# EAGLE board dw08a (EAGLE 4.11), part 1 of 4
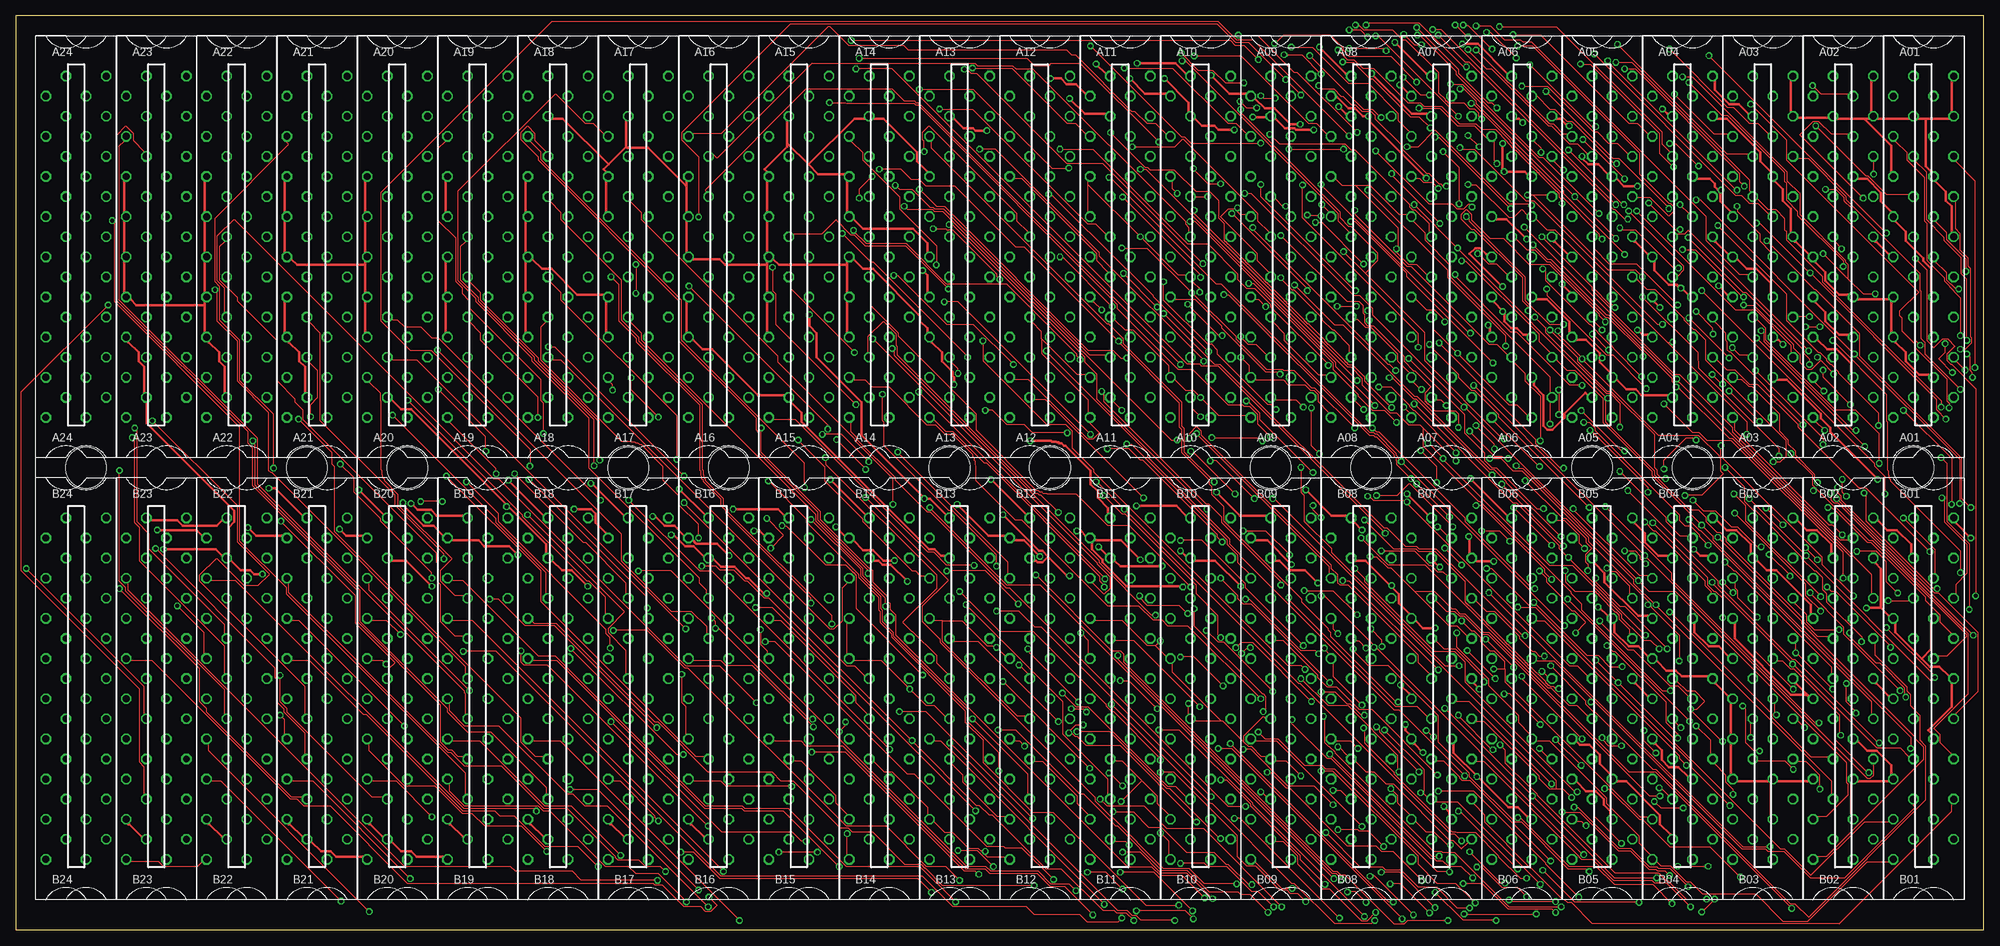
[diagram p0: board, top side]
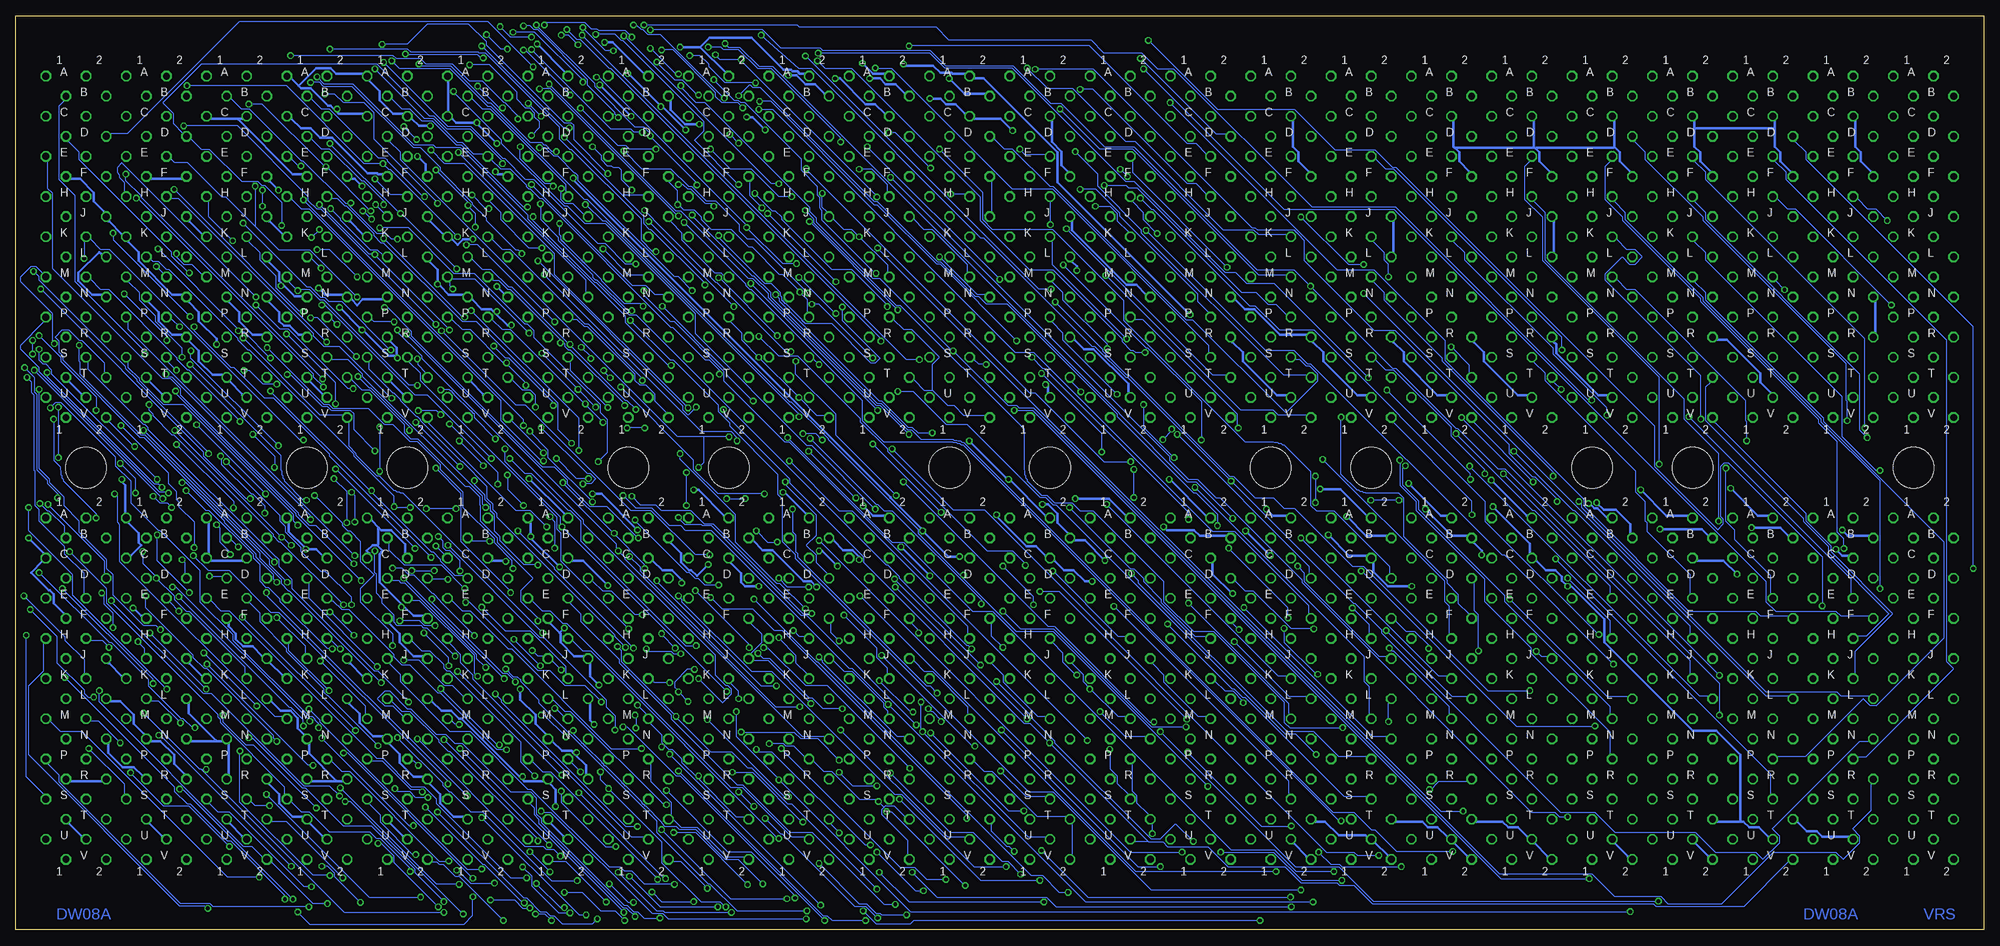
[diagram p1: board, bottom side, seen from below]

Size 311.15 x 144.46 mm. Coordinates in mm from the lower left corner, seen from the top.
Outline: 0,0 311.15,0 311.15,144.46 0,144.46 0,0
Copper layers (1*16): Top 0.035mm / dielectric 1.5mm / Bottom 0.035mm
Design rules "sierraproto": minimum track width 6mil, minimum drill 24mil, track to track 6mil, track to pad 6mil, pad to pad 10mil, via to via 6mil, smd to smd 6mil, copper to edge 25mil, drill to drill 10mil, minimum pad ring 10mil, minimum via ring 8mil, stop-mask expansion 0mil, vias tented up to drill 0mil, thermal gap 10mil
Net classes: 1 supply: width 0.381 mm

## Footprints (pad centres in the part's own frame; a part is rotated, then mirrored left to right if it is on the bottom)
H807 = drill 1.092 octagon: A1 4.763,28.575; A2 -1.587,28.575; B1 1.587,25.4; B2 -4.763,25.4; C1 4.763,22.225; C2 -1.587,22.225; D1 1.587,19.05; D2 -4.763,19.05; E1 4.763,15.875; E2 -1.587,15.875; F1 1.587,12.7; F2 -4.763,12.7; H1 4.763,9.525; H2 -1.587,9.525; J1 1.587,6.35; J2 -4.763,6.35; K1 4.763,3.175; K2 -1.587,3.175; L1 1.587,0; L2 -4.763,0; M1 4.763,-3.175; M2 -1.587,-3.175; N1 1.587,-6.35; N2 -4.763,-6.35; P1 4.763,-9.525; P2 -1.587,-9.525; R1 1.587,-12.7; R2 -4.763,-12.7; S1 4.763,-15.875; S2 -1.587,-15.875; T1 1.587,-19.05; T2 -4.763,-19.05; U1 4.763,-22.225; U2 -1.587,-22.225; V1 1.587,-25.4; V2 -4.763,-25.4
CBLOCK = hole 6.452: 7.938,68.263; 42.862,68.263

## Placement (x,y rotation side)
A01  M903  [H807]  301.62,106.36 0 top
A02  M903  [H807]  288.93,106.36 0 top
A03  M903  [H807]  276.23,106.36 0 top
A04  M903  [H807]  263.52,106.36 0 top
A05  M903  [H807]  250.82,106.36 0 top
A06  M907  [H807]  238.12,106.36 0 top
A07  M651  [H807]  225.43,106.36 0 top
A08  M651  [H807]  212.72,106.36 0 top
A09  M651  [H807]  200.03,106.36 0 top
A10  M651  [H807]  187.32,106.36 0 top
A11  M651  [H807]  174.62,106.36 0 top
A12  M651  [H807]  161.93,106.36 0 top
A13  W011  [H807]  149.22,106.36 0 top
A14  W011  [H807]  136.53,106.36 0 top
A15  W011  [H807]  123.83,106.36 0 top
A16  W011  [H807]  111.12,106.36 0 top
A17  W011  [H807]  98.42,106.36 0 top
A18  W011  [H807]  85.72,106.36 0 top
A19  W011  [H807]  73.03,106.36 0 top
A20  W011  [H807]  60.33,106.36 0 top
A21  W011  [H807]  47.62,106.36 0 top
A22  W011  [H807]  34.92,106.36 0 top
A23  W011  [H807]  22.23,106.36 0 top
A24  H807  [H807]  9.53,106.36 0 top
B01  M903  [H807]  301.62,36.51 0 top
B02  M903  [H807]  288.93,36.51 0 top
B03  M903  [H807]  276.23,36.51 0 top
B04  M903  [H807]  263.52,36.51 0 top
B05  M903  [H807]  250.82,36.51 0 top
B06  M101  [H807]  238.12,36.51 0 top
B07  M907  [H807]  225.43,36.51 0 top
B08  M651  [H807]  212.72,36.51 0 top
B09  M651  [H807]  200.03,36.51 0 top
B10  M651  [H807]  187.32,36.51 0 top
B11  M651  [H807]  174.62,36.51 0 top
B12  M651  [H807]  161.93,36.51 0 top
B13  M651  [H807]  149.22,36.51 0 top
B14  M651  [H807]  136.53,36.51 0 top
B15  M651  [H807]  123.83,36.51 0 top
B16  M517  [H807]  111.12,36.51 0 top
B17  M517  [H807]  98.42,36.51 0 top
B18  M517  [H807]  85.72,36.51 0 top
B19  M517  [H807]  73.03,36.51 0 top
B20  M517  [H807]  60.33,36.51 0 top
B21  M517  [H807]  47.62,36.51 0 top
B22  M517  [H807]  34.92,36.51 0 top
B23  M517  [H807]  22.23,36.51 0 top
B24  H807  [H807]  9.53,36.51 0 top
U$1  [CBLOCK]  3.17,4.76 0 top
U$2  [CBLOCK]  53.98,4.76 0 top
U$3  [CBLOCK]  104.78,4.76 0 top
U$4  [CBLOCK]  155.57,4.76 0 top
U$5  [CBLOCK]  206.38,4.76 0 top
U$6  [CBLOCK]  257.18,4.76 0 top

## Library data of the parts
A01-A09 A10-A24 B01-B09 B10-B24 U$1-U$6 = dec-m

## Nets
-15V [supply]: A07.B2 A08.B2 A09.B2 A10.B2 A11.B2 A12.B2 B08.B2 B09.B2 B10.B2 B11.B2 B12.B2 B13.B2 B14.B2 B15.B2 B16.B2 B17.B2 B18.B2 B19.B2 B20.B2 B21.B2 B22.B2 B23.B2
A06U1: A06.U1 A07.F2 A07.J2 A07.M2 A08.F2 A08.J2 A08.M2 A09.F2 A09.J2 A09.M2 A10.F2 A10.J2 A10.M2 A10.P2 A11.F2 A11.J2 A11.M2 A12.F2 A12.J2 A12.M2 B06.C1
A06V1: A06.V1 A07.P2 A07.T2 A07.V2 A08.P2 A08.T2 A08.V2 A09.P2 A09.T2 A09.V2 A10.T2 A10.V2 A11.P2 A11.T2 A11.V2 A12.P2 A12.T2 A12.V2
B07U1: B07.U1 B08.F2 B08.J2 B08.M2 B08.P2 B08.T2 B08.V2 B09.F2 B09.J2 B09.M2 B09.P2 B09.T2 B09.V2 B10.F2 B10.J2 B10.M2 B11.F2 B11.J2 B11.M2 B12.F2 B12.J2 B12.M2 B13.F2 B13.J2 B13.M2 B14.F2 B14.J2 B14.M2 B15.F2 B15.J2 B15.M2
B07V1: B07.V1 B10.P2 B10.T2 B10.V2 B11.P2 B11.T2 B11.V2 B12.P2 B12.T2 B12.V2 B13.P2 B13.T2 B13.V2 B14.P2 B14.T2 B14.V2 B15.P2
GND [supply]: A01.A1 A01.C1 A01.C2 A01.F1 A01.F2 A01.J2 A01.K1 A01.L2 A01.N1 A01.N2 A01.R1 A01.R2 A01.T1 A01.U2 A02.A1 A02.C1 A02.C2 A02.F1 A02.F2 A02.J2 A02.K1 A02.L2 A02.N1 A02.N2 A02.R1 A02.R2 A02.T1 A02.U2 A03.A1 A03.C1 A03.C2 A03.F1 A03.F2 A03.J2 A03.K1 A03.L2 A03.N1 A03.N2 A03.R1 A03.R2 A03.T1 A03.U2 A04.A1 A04.C1 A04.C2 A04.F1 A04.F2 A04.J2 A04.K1 A04.L2 A04.N1 A04.N2 A04.R1 A04.R2 A04.T1 A04.U2 A05.A1 A05.C1 A05.C2 A05.F1 A05.F2 A05.J2 A05.K1 A05.L2 A05.N1 A05.N2 A05.R1 A05.R2 A05.T1 A05.U2 A06.A1 A06.C1 A06.C2 A06.F1 A06.F2 A06.J2 A06.K1 A06.L2 A06.N1 A06.N2 A06.R1 A06.R2 A06.T1 A06.U2 A07.C2 A08.C2 A09.C2 A10.C2 A11.C2 A12.C2 A13.C2 A13.F2 A13.J2 A13.L2 A13.N2 A13.R2 A13.U2 A14.C2 A14.F2 A14.J2 A14.L2 A14.N2 A14.R2 A14.U2 A15.C2 A15.F2 A15.J2 A15.L2 A15.N2 A15.R2 A15.U2 A16.C2 A16.F2 A16.J2 A16.L2 A16.N2 A16.R2 A16.U2 A17.C2 A17.F2 A17.J2 A17.L2 A17.N2 A17.R2 A17.U2 A18.C2 A18.F2 A18.J2 A18.L2 A18.N2 A18.R2 A18.U2 A19.C2 A19.F2 A19.J2 A19.L2 A19.N2 A19.R2 A19.U2 A20.C2 A20.F2 A20.J2 A20.L2 A20.N2 A20.R2 A20.U2 A21.C2 A21.F2 A21.J2 A21.L2 A21.N2 A21.R2 A21.U2 A22.C2 A22.F2 A22.J2 A22.L2 A22.N2 A22.R2 A22.U2 A23.C2 A23.F2 A23.J2 A23.L2 A23.N2 A23.R2 A23.U2 B01.A1 B01.C1 B01.C2 B01.F1 B01.F2 B01.J2 B01.K1 B01.L2 B01.N1 B01.N2 B01.R1 B01.R2 B01.T1 B01.U2 B02.A1 B02.C1 B02.C2 B02.F1 B02.F2 B02.J2 B02.K1 B02.L2 B02.N1 B02.N2 B02.R1 B02.R2 B02.T1 B02.U2 B03.A1 B03.C1 B03.C2 B03.F1 B03.F2 B03.J2 B03.K1 B03.L2 B03.N1 B03.N2 B03.R1 B03.R2 B03.T1 B03.U2 B04.A1 B04.C1 B04.C2 B04.F1 B04.F2 B04.J2 B04.K1 B04.L2 B04.N1 B04.N2 B04.R1 B04.R2 B04.T1 B04.U2 B05.A1 B05.C1 B05.C2 B05.F1 B05.F2 B05.J2 B05.K1 B05.L2 B05.N1 B05.N2 B05.R1 B05.R2 B05.T1 B05.U2 B06.C2 B06.T1 B07.A1 B07.C1 B07.C2 B07.F1 B07.F2 B07.J2 B07.K1 B07.L2 B07.N1 B07.N2 B07.R1 B07.R2 B07.T1 B07.U2 B08.C2 B09.C2 B10.C2 B11.C2 B12.C2 B13.C2 B14.C2 B15.C2 B16.C2 B16.T2 B16.U2 B16.V2 B17.C2 B17.T2 B17.U2 B17.V2 B18.C2 B18.T2 B18.U2 B18.V2 B19.C2 B19.T2 B19.U2 B19.V2 B20.C2 B20.T2 B20.U2 B20.V2 B21.C2 B21.T2 B21.U2 B21.V2 B22.C2 B22.T2 B22.U2 B23.C2 B23.T2 B23.U2
I_3CYCLE: A05.K2 B05.K2 B19.F2
I_AC00: A03.B1 B03.B1 B16.D2
I_AC01: A03.D1 B03.D1 B16.F2
I_AC02: A03.E1 B03.E1 B16.J2
I_AC03: A03.H1 B03.H1 B16.L2
I_AC04: A03.J1 B03.J1 B16.N2
I_AC05: A03.L1 B03.L1 B16.R2
I_AC06: A03.M1 B03.M1 B17.D2
I_AC07: A03.P1 B03.P1 B17.F2
I_AC08: A03.S1 B03.S1 B17.J2
I_AC09: A03.D2 B03.D2 B17.L2
I_AC10: A03.E2 B03.E2 B17.N2
I_AC11: A03.H2 B03.H2 B17.R2
I_ACCEPT: A04.S2 B04.S2 B07.S2 B15.H2
I_ACCLR: A03.P2 B03.P2 B18.J2
I_ADD00: A04.B1 B04.B1 B20.D2
I_ADD01: A04.D1 B04.D1 B20.F2
I_ADD02: A04.E1 B04.E1 B20.J2
I_ADD03: A04.H1 B04.H1 B20.L2
I_ADD04: A04.J1 B04.J1 B20.N2
I_ADD05: A04.L1 B04.L1 B20.R2
I_ADD06: A04.M1 B04.M1 B21.D2
I_ADD07: A04.P1 B04.P1 B21.F2
I_ADD08: A04.S1 B04.S1 B21.J2
I_ADD09: A04.D2 B04.D2 B21.L2
I_ADD10: A04.E2 B04.E2 B21.N2
I_ADD11: A04.H2 B04.H2 B21.R2
I_BAC00: A01.B1 B01.B1 B07.B1 B10.H2
I_BAC01: A01.D1 B01.D1 B07.D1 B10.N2
I_BAC02: A01.E1 B01.E1 B07.E1 B10.U2
I_BAC03: A01.H1 B01.H1 B07.H1 B11.H2
I_BAC04: A01.J1 B01.J1 B07.J1 B11.N2
I_BAC05: A01.L1 B01.L1 B07.L1 B11.U2
I_BAC06: A01.M1 B01.M1 B07.M1 B12.H2
I_BAC07: A01.P1 B01.P1 B07.P1 B12.N2
I_BAC08: A01.S1 B01.S1 B07.S1 B12.U2
I_BAC09: A01.D2 B01.D2 B07.D2 B13.H2
I_BAC10: A01.E2 B01.E2 B07.E2 B13.N2
I_BAC11: A01.H2 B01.H2 B07.H2 B13.U2
I_BREAK: A04.P2 B04.P2 B07.P2 B14.U2 B22.V2 B23.V2
I_BRKRQ: A04.K2 B04.K2 B18.N2
I_CAINCR: A05.M2 B05.M2 B19.J2
I_DATA00: A05.B1 B05.B1 B22.D2
I_DATA01: A05.D1 B05.D1 B22.F2
I_DATA02: A05.E1 B05.E1 B22.J2
I_DATA03: A05.H1 B05.H1 B22.L2
I_DATA04: A05.J1 B05.J1 B22.N2
I_DATA05: A05.L1 B05.L1 B22.R2
I_DATA06: A05.M1 B05.M1 B23.D2
I_DATA07: A05.P1 B05.P1 B23.F2
I_DATA08: A05.S1 B05.S1 B23.J2
I_DATA09: A05.D2 B05.D2 B23.L2
I_DATA10: A05.E2 B05.E2 B23.N2
I_DATA11: A05.H2 B05.H2 B23.R2
I_DATAIN: A04.M2 B04.M2 B18.R2
I_EXTA0: A05.V2 B05.V2 B19.R2
I_EXTA1: A05.T2 B05.T2 B19.N2
I_EXTA2: A05.S2 B05.S2 B19.L2
I_INIT: A01.V2 A04.V2 B01.V2 B04.V2 B06.N1
I_IOP1: A01.K2 B01.K2 B06.A1
I_IOP2: A01.M2 B01.M2 B06.D1
I_IOP4: A01.P2 B01.P2 B06.F1
I_IRQ: A03.M2 B03.M2 B18.F2
I_LINE: A03.V2 B03.V2 B18.L2
I_MB00: A02.B1 A06.B1 A07.H2 B02.B1
I_MB01: A02.D1 A06.D1 A07.N2 B02.D1
I_MB02: A02.E1 A06.E1 A07.U2 B02.E1
I_MB03: A02.J1 A06.J1 A08.N2 B02.J1
I_MB03\: A02.H1 A06.H1 A08.H2 B02.H1
I_MB04: A02.M1 A06.M1 A09.H2 B02.M1
I_MB04\: A02.L1 A06.L1 A08.U2 B02.L1
I_MB05: A02.S1 A06.S1 A09.U2 B02.S1
I_MB05\: A02.P1 A06.P1 A09.N2 B02.P1
I_MB06: A02.E2 A06.E2 A10.N2 B02.E2
I_MB06\: A02.D2 A06.D2 A10.H2 B02.D2
I_MB07: A02.K2 A06.K2 A11.H2 B02.K2
I_MB07\: A02.H2 A06.H2 A10.U2 B02.H2
I_MB08: A02.P2 A06.P2 A11.U2 B02.P2
I_MB08\: A02.M2 A06.M2 A11.N2 B02.M2
I_MB09: A02.S2 A06.S2 A12.H2 B02.S2
I_MB10: A02.T2 A06.T2 A12.N2 B02.T2
I_MB11: A02.V2 A06.V2 A12.U2 B02.V2
I_MBINCR: A04.T2 B04.T2 B19.D2
I_RUN: A03.S2 B03.S2 B07.K2 B14.H2
I_SKIP: A03.K2 B03.K2 B18.D2
I_TS1: A01.T2 B01.T2 B06.L1
I_TS3: A01.S2 B01.S2 B06.J1
I_TT_INST: A03.T2 B03.T2 B07.M2 B14.N2
I_WCOV: A05.P2 B05.P2 B07.T2 B15.N2
N$1: B06.B1 B08.H2
N$2: B06.E1 B08.N2
N$3: B06.H1 B08.U2
N$4: B06.K1 B09.H2
N$5: B06.M1 B09.N2
N$6: B06.P1 B09.U2
O_3CYCLE: A22.K2 B19.H2
O_AC00: A17.D2 B16.E2
O_AC01: A17.E2 B16.H2
O_AC02: A17.H2 B16.K2
O_AC03: A17.K2 B16.M2
O_AC04: A17.M2 B16.P2
O_AC05: A17.P2 B16.S2
O_AC06: A17.S2 B17.E2
O_AC07: A17.T2 B17.H2
O_AC08: A17.V2 B17.K2
O_AC09: A18.D2 B17.M2
O_AC10: A18.E2 B17.P2
O_AC11: A18.H2 B17.S2
O_ACCEPT: A20.S2 B15.D2
O_ACCLR: A18.P2 B18.K2
O_ADD00: A19.D2 B20.E2
O_ADD01: A19.E2 B20.H2
O_ADD02: A19.H2 B20.K2
O_ADD03: A19.K2 B20.M2
O_ADD04: A19.M2 B20.P2
O_ADD05: A19.P2 B20.S2
O_ADD06: A19.S2 B21.E2
O_ADD07: A19.T2 B21.H2
O_ADD08: A19.V2 B21.K2
O_ADD09: A20.D2 B21.M2
O_ADD10: A20.E2 B21.P2
O_ADD11: A20.H2 B21.S2
O_BAC00: A13.D2 B10.D2
O_BAC01: A13.E2 B10.K2
O_BAC02: A13.H2 B10.S2
O_BAC03: A13.K2 B11.D2
O_BAC04: A13.M2 B11.K2
O_BAC05: A13.P2 B11.S2
O_BAC06: A13.S2 B12.D2
O_BAC07: A13.T2 B12.K2
O_BAC08: A13.V2 B12.S2
O_BAC09: A14.D2 B13.D2
O_BAC10: A14.E2 B13.K2
O_BAC11: A14.H2 B13.S2
O_BREAK: A20.P2 B14.S2
O_BRKRQ: A20.K2 B18.P2
O_CAINCR: A22.M2 B19.K2
O_DATA00: A21.D2 B22.E2
O_DATA01: A21.E2 B22.H2
O_DATA02: A21.H2 B22.K2
O_DATA03: A21.K2 B22.M2
O_DATA04: A21.M2 B22.P2
O_DATA05: A21.P2 B22.S2
O_DATA06: A21.S2 B23.E2
O_DATA07: A21.T2 B23.H2
O_DATA08: A21.V2 B23.K2
O_DATA09: A22.D2 B23.M2
O_DATA10: A22.E2 B23.P2
O_DATA11: A22.H2 B23.S2
O_DATAIN: A20.M2 B18.S2
O_EXTA0: A23.H2 B19.S2
O_EXTA1: A23.E2 B19.P2
O_EXTA2: A23.D2 B19.M2
O_INIT: A14.V2 B09.S2
O_IOP1: A14.K2 B08.D2
O_IOP2: A14.M2 B08.K2
O_IOP4: A14.P2 B08.S2
O_IRQ: A18.M2 B18.H2
O_LINE: A18.V2 B18.M2
O_MB00: A07.D2 A15.D2
O_MB01: A07.K2 A15.E2
O_MB02: A07.S2 A15.H2
O_MB03: A08.K2 A15.M2
O_MB03\: A08.D2 A15.K2
O_MB04: A09.D2 A15.S2
O_MB04\: A08.S2 A15.P2
O_MB05: A09.S2 A15.V2
O_MB05\: A09.K2 A15.T2
O_MB06: A10.K2 A16.E2
O_MB06\: A10.D2 A16.D2
O_MB07: A11.D2 A16.K2
O_MB07\: A10.S2 A16.H2
O_MB08: A11.S2 A16.P2
O_MB08\: A11.K2 A16.M2
O_MB09: A12.D2 A16.S2
O_MB10: A12.K2 A16.T2
O_MB11: A12.S2 A16.V2
O_MBINCR: A20.T2 B19.E2
O_RUN: A18.S2 B14.D2
O_SKIP: A18.K2 B18.E2
O_TS1: A14.T2 B09.K2
O_TS3: A14.S2 B09.D2
O_TT_INST: A18.T2 B14.K2
O_WCOV: A22.P2 B15.K2
VCC [supply]: A06.A2 A07.A2 A08.A2 A09.A2 A10.A2 A11.A2 A12.A2 B06.A2 B07.A2 B08.A2 B09.A2 B10.A2 B11.A2 B12.A2 B13.A2 B14.A2 B15.A2 B16.A2 B17.A2 B18.A2 B19.A2 B20.A2 B21.A2 B22.A2 B23.A2

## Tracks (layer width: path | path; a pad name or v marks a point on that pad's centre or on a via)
-15V  (via drill 0.61)
  Top 0.381: v22.35,63.18 28.57,63.18 29.46,62.29 B22.B2 | v36.7,63.56 37.97,62.29 42.16,62.29 B21.B2 | v51.18,63.31 52.2,62.29 54.86,62.29 B20.B2 | v79.38,59.24 77.98,60.64 74.04,60.64 73.15,61.53 68.96,61.53 B19.B2 67.56,62.29 66.04,63.82 64.52,63.82 61.21,67.12 v61.21,67.5 | v100.71,65.34 101.09,65.34 102.62,63.82 104.14,63.82 105.66,62.29 B16.B2 107.06,61.53 107.57,61.02 110.87,61.02 v112.78,59.12 | v88.27,66.48 90.93,66.48 91.69,65.72 91.69,64.33 93.34,62.67 B17.B2 | v163.58,134.56 165.23,134.56 166.12,133.67 167.64,133.67 169.16,132.14 A11.B2 | v176.15,134.56 178.56,132.14 181.86,132.14 A10.B2 | v188.98,135.06 191.9,132.14 194.56,132.14 A09.B2 195.96,131.38 197.49,129.86 199.01,129.86 201.55,127.32 v203.07,127.32 | v218.82,133.54 220.09,132.27 A07.B2 | A08.B2 208.66,131.89 210.69,129.86 211.71,129.86 212.98,128.59 v213.87,128.59 214.12,128.21 214.12,127.7 v223.01,118.81 | v129.67,63.69 131.06,62.29 B14.B2 132.46,61.53 133.99,60.01 135.51,60.01 137.16,58.36 v138.94,58.36 | v148.84,67.25 153.8,62.29 156.46,62.29 B12.B2 157.86,61.53 159.38,61.53 v161.93,58.99 | v177.8,58.48 174.75,61.53 170.56,61.53 B11.B2 | v201.68,57.72 197.87,61.53 195.96,61.53 B09.B2 | v184.53,54.17 184.4,54.29 175.64,54.29 171.83,58.1 171.83,58.48 170.18,60.13 170.18,61.15 B11.B2 | v167.77,63.06 168.4,63.06 169.16,62.29 B11.B2 | v116.71,63.06 117.6,63.06 118.36,62.29 B15.B2
  Bottom 0.381: v22.35,63.18 21.46,62.29 18.16,62.29 B23.B2 | v36.7,63.56 32.13,63.56 30.86,62.29 B22.B2 | v51.18,63.31 44.58,63.31 43.56,62.29 B21.B2 | v79.38,59.24 79.38,59.88 80.64,61.15 B18.B2 81.66,62.29 84.07,62.29 v88.27,66.48 | v100.71,65.34 97.66,62.29 94.36,62.29 B17.B2 | v61.21,67.5 60.07,66.36 58.17,66.36 55.88,64.07 55.88,62.67 B20.B2 | v163.58,134.56 161.16,132.14 157.86,132.14 A12.B2 | v176.15,134.56 174.5,134.56 173.61,133.67 172.09,133.67 170.56,132.14 A11.B2 | v188.98,135.06 187.71,135.06 186.31,133.67 184.78,133.67 183.26,132.14 A10.B2 | v203.07,127.32 205.36,127.32 207.65,129.6 207.65,131 A08.B2 | v213.87,128.59 v218.82,133.54 | v129.67,63.69 129.16,63.18 124.84,63.18 123.95,62.29 119.76,62.29 B15.B2 | v138.94,58.36 142.11,61.53 143.76,61.53 B13.B2 144.78,62.67 146.43,64.33 146.43,65.72 147.96,67.25 v148.84,67.25 | v177.8,58.48 177.8,58.99 178.82,60.01 180.34,60.01 181.86,61.53 B10.B2 | v201.68,57.72 203.45,55.94 204.34,56.83 204.72,56.83 205.99,58.1 205.99,59.5 207.65,61.15 B08.B2 | v184.53,54.17 185.42,55.05 186.56,55.05 191.52,60.01 193.04,60.01 194.56,61.53 B09.B2 | v161.93,58.99 163.7,58.99 v167.77,63.06 168.02,63.44 172.85,68.26 172.85,68.39 223.01,118.56 v223.01,118.81 | v116.71,63.06 v112.78,59.12
A06U1  (via drill 0.61)
  Top 0.152: v183.64,116.39 182.88,117.16 182.88,118.3 A10.F2 | A12.F2 157.86,118.68 159.13,118.68 170.94,106.87 170.94,105.73 172.72,103.95 A11.M2 | v187.2,100.78 187.2,101.28 186.06,102.42 A10.M2 185.04,103.57 183.77,103.57 v177.8,109.54 169.54,117.79 | 169.54,117.79 169.54,113.47 A11.J2 | 169.54,117.79 169.54,118.3 A11.F2 | v234.95,70.42 v244.73,60.64 | v242.57,79.95 242.57,83.38 A06.U1 242.57,84.9 242.57,87.44 226.82,103.19 226.82,104.97 222.76,109.03 222.76,110.17 220.98,111.95 A07.J2 219.96,113.09 218.69,113.09 214.12,117.67 211.84,117.67 | 193.17,113.47 192.66,113.98 191.77,113.98 190.5,112.71 196.34,106.87 196.34,105.73 198.12,103.95 A09.M2 | 193.17,113.47 193.55,113.09 194.56,113.09 A09.J2 | 193.17,113.47 v193.17,114.11 | A07.M2 223.14,103.57 221.49,105.22 220.22,105.22 218.31,107.12 v218.31,107.63 218.57,108.01 218.57,110.93 211.84,117.67 | 211.84,117.67 209.68,117.67 208.66,118.68 A08.F2 | v224.92,117.16 224.03,118.05 222.63,118.05 222,118.68 221.36,118.68 A07.F2 | v206.5,114.62 207.65,113.47 A08.J2
  Bottom 0.152: A12.J2 156.84,113.47 156.84,118.3 A12.F2 | A11.M2 173.35,103.95 173.35,105.09 v177.8,109.54 178.94,110.68 180.21,110.68 181.86,112.33 A10.J2 182.88,113.47 183.64,114.24 v183.64,116.39 | A10.P2 186.06,97.6 186.06,99.63 v187.2,100.78 187.45,101.16 189.87,103.57 190.37,103.57 194.69,107.89 195.2,107.89 197.99,110.68 201.17,110.68 202.69,112.2 202.69,112.58 203.84,113.73 205.49,113.73 206.12,114.36 v206.5,114.62 206.5,116.78 208.03,118.3 A08.F2 | A12.M2 160.66,103.95 160.66,105.09 166.24,110.68 167.51,110.68 169.16,112.33 A11.J2 | v244.73,60.64 243.46,59.37 243.46,59.24 B06.C1 | v234.95,70.42 234.95,72.33 v242.57,79.95 | A09.M2 199.14,103.57 199.39,103.57 199.64,103.82 200.66,103.82 205.87,109.03 205.87,110.17 207.65,111.95 A08.J2 | v193.17,114.11 195.07,116.01 195.07,118.3 A09.F2 | v218.31,107.63 214.25,103.57 211.84,103.57 A08.M2 | v224.92,117.16 224.92,115.38 224.28,114.75 223.01,114.75 221.36,113.09 A07.J2
A06V1  (via drill 0.61)
  Top 0.152: v219.46,82.61 220.34,81.72 A07.V2 | v222.25,85.41 222.12,85.41 220.98,86.55 A07.T2 220.34,88.08 218.57,89.85 218.57,91 214.38,95.19 213.49,95.19 212.22,96.46 211.84,96.46 A08.P2 | A07.P2 224.16,96.08 224.16,94.93 v227.97,91.12 236.09,83 237.36,83 239.01,81.34 A06.V1 | A08.V2 207.65,81.72 205.87,83.5 205.87,84.64 205.23,85.28 204.72,85.28 203.84,86.17 201.17,86.17 200.41,86.93 195.96,86.93 A09.T2 194.94,88.08 194.94,89.22 v193.68,90.49 | A08.T2 207.26,87.69 205.99,87.69 200.53,93.15 200.53,94.3 198.75,96.08 A09.P2 | 162.18,93.41 162.18,94.55 160.66,96.08 A12.P2 | 162.18,93.41 162.18,91.12 169.54,83.76 169.54,81.72 A11.V2 169.67,80.2 171.32,78.55 170.31,77.53 169.54,77.53 160.15,86.93 157.86,86.93 A12.T2 | 162.18,93.41 167.89,87.69 169.16,87.69 A11.T2 | A11.P2 173.74,96.46 175.39,94.81 176.66,94.81 182.25,89.22 182.25,88.08 A10.T2 183.26,86.93 184.91,85.28 186.18,85.28 v187.32,84.14 190.12,81.34 194.56,81.34 A09.V2
  Bottom 0.152: v219.46,82.61 v222.25,85.41 222.63,85.66 222.63,85.79 v227.97,91.12 | A10.V2 183.26,81.34 184.53,81.34 v187.32,84.14 v193.68,90.49 196.34,93.15 196.34,94.3 198.12,96.08 A09.P2 | 166.24,85.28 163.83,82.87 162.81,82.87 161.29,81.34 157.86,81.34 A12.V2 | 166.24,85.28 167.51,85.28 169.16,86.93 A11.T2 | 166.24,85.28 166.24,89.34 165.1,90.49 169.42,94.81 170.69,94.81 172.34,96.46 A11.P2 | A07.P2 223.14,96.46 222.38,96.46 221.23,95.31 220.73,95.31 213.23,87.82 213.23,86.81 212.47,86.04 211.46,86.04 210.06,84.64 210.06,83.5 208.28,81.72 A08.V2
B07U1  (via drill 0.61)
  Top 0.152: v117.73,47.43 117.73,45.15 118.75,44.13 118.75,43.62 B15.J2 | B15.F2 119.76,48.83 121.03,48.83 132.84,37.02 132.84,35.88 134.62,34.1 B14.M2 | B14.F2 131.44,48.45 131.44,43.62 B14.J2 132.46,42.48 136.91,42.48 v141.35,38.04 144.02,35.37 145.29,35.37 146.94,33.72 B13.M2 | 146.56,48.83 149.61,48.83 153.54,44.9 154.81,44.9 v155.07,44.64 156.46,43.24 B12.J2 | 146.56,48.83 145.16,48.83 B13.F2 | 146.56,48.83 146.56,45.53 158.37,33.72 159.64,33.72 B12.M2 | 180.21,44.9 178.94,44.9 175.01,48.83 170.56,48.83 B11.F2 | 180.21,44.9 181.86,43.24 B10.J2 182.88,42.1 182.88,40.7 190.63,32.96 | 180.21,44.9 v180.97,45.66 | 194.18,29.65 194.94,28.89 195.45,28.89 196.98,27.37 197.74,27.37 B09.P2 199.14,26.61 200.91,26.61 v203.2,24.32 | 194.18,29.65 194.18,30.67 197.23,33.72 197.74,33.21 B09.M2 | 190.63,32.96 190.88,32.96 194.18,29.65 | 190.63,32.96 186.44,32.96 B10.M2 185.42,34.1 v185.42,35.75 | v212.85,35.5 208.28,40.07 208.28,42.1 B08.J2 207.65,43.62 206.88,44.39 v206.88,44.51 | v209.04,46.8 208.28,47.56 208.28,48.45 B08.F2 | v201.8,6.54 200.15,6.54 195.96,10.73 B09.V2 | B07.U1 229.62,13.78 228.6,12.76 227.2,14.16 226.69,14.16 217.81,23.05 216.66,23.05 214.76,24.96 213.49,24.96 211.84,26.61 B08.P2 210.57,27.5 209.17,28.89 v209.04,28.89 | v168.4,46.93 169.54,45.78 169.54,43.62 B11.J2
  Bottom 0.152: v117.73,47.43 118.75,48.45 B15.F2 | 141.22,38.04 142.37,39.18 142.37,40.32 144.15,42.1 B13.J2 | 141.22,38.04 136.91,33.72 135.64,33.72 B14.M2 | B15.M2 122.94,33.72 124.21,33.72 129.67,39.18 129.67,40.32 131.44,42.1 B14.J2 | B12.M2 160.66,34.1 160.66,35.24 166.24,40.83 167.51,40.83 169.16,42.48 B11.J2 | B13.M2 148.34,33.72 149.61,33.72 155.07,39.18 155.07,40.32 156.84,42.1 B12.J2 | v155.07,44.64 156.84,46.42 156.84,48.45 B12.F2 | v141.35,38.04 141.22,38.04 | B11.M2 173.35,34.1 173.35,34.61 173.99,35.24 173.99,35.88 178.94,40.83 180.21,40.83 181.86,42.48 B10.J2 | v180.97,45.66 182.25,46.93 182.25,48.45 B10.F2 | B09.F2 194.94,48.45 193.17,46.67 193.17,45.4 194.94,43.62 B09.J2 194.56,42.48 192.15,42.48 v185.42,35.75 | 203.45,24.07 205.87,26.48 205.87,26.99 207.39,28.51 207.9,28.51 208.66,29.27 | 203.45,24.07 197.23,17.84 195.96,17.84 B09.T2 | 208.66,29.27 209.04,29.65 209.04,30.8 210.82,32.58 B08.M2 211.46,34.1 v212.85,35.5 | v209.04,46.8 209.04,46.67 v206.88,44.51 | B09.V2 195.96,11.49 198.75,11.49 203.45,16.19 205.99,16.19 207.26,17.46 B08.T2 207.52,18.1 207.52,20.13 210.82,23.43 210.82,26.23 B08.P2 | v201.8,6.54 205.99,10.73 207.26,10.73 B08.V2 | 208.66,29.27 v209.04,28.89 | 203.45,24.07 v203.2,24.32 | v168.4,46.93 168.4,47.31 169.54,48.45 B11.F2
B07V1  (via drill 0.61)
  Top 0.152: B12.T2 156.46,17.84 155.19,17.84 149.73,23.3 149.73,24.45 147.96,26.23 B13.P2 | 152.65,12.38 152.15,12.89 150.62,12.89 148.08,15.43 146.81,15.43 145.16,17.08 B13.T2 144.15,18.22 144.15,19.37 138.56,24.96 137.29,24.96 135.64,26.61 B14.P2 | 152.65,12.38 153.54,11.49 156.46,11.49 B12.V2 | v131.44,15.18 131.44,11.87 B14.V2 | B15.P2 122.94,26.61 124.21,26.61 129.67,21.14 129.67,20 131.44,18.22 B14.T2 | 152.65,12.38 v153.29,12.38 | v180.97,15.3 182.25,14.03 182.25,11.87 B10.V2 | 178.05,23.56 180.47,21.14 180.47,20 182.25,18.22 B10.T2 | 178.05,23.56 175.01,26.61 173.74,26.61 B11.P2 | B12.P2 161.04,26.61 162.31,26.61 167.77,21.14 167.77,20 169.54,18.22 B11.T2 | v174.75,20.26 178.05,23.56 | v217.81,4.38 217.04,4.38 v192.02,29.4
  Bottom 0.152: B13.V2 144.15,11.87 144.15,16.7 B13.T2 145.16,17.84 149.61,17.84 156.72,24.96 157.99,24.96 159.64,26.61 B12.P2 | v131.44,15.18 131.44,16.7 B14.T2 132.08,18.22 133.86,20 133.86,21.14 134.62,21.91 134.62,26.23 B14.P2 | v153.29,12.38 154.05,13.14 154.43,13.14 156.84,15.56 156.84,16.7 B12.T2 | v180.97,15.3 180.97,15.43 182.25,16.7 B10.T2 | 173.86,19.37 173.61,19.62 173.48,19.49 172.21,19.49 170.56,17.84 B11.T2 | 173.86,19.37 174.24,18.99 174.24,18.22 170.18,14.16 170.18,11.87 B11.V2 | 173.86,19.37 v174.75,20.26 175.13,20.51 177.67,20.51 182.12,24.96 183.39,24.96 185.04,26.61 B10.P2 186.44,27.37 188.09,29.02 189.36,29.02 189.74,29.4 v192.02,29.4 | v217.81,4.38 224.16,10.73 226.31,10.73 B07.V1
GND  (via drill 0.61)
  Top 0.381: A01.T1 302.51,87.69 300.99,87.69 298.83,89.85 298.83,91.25 297.18,92.9 A01.R2 296.55,94.42 296.55,99.25 A01.N2 296.16,99.63 291.21,99.63 A02.N1 289.81,100.39 288.29,100.39 286.13,102.55 286.13,103.95 284.48,105.6 A02.L2 283.46,106.74 281.43,108.78 281.31,108.78 A03.K1 280.67,110.3 280.67,113.98 279.4,115.25 279.4,117.03 278.13,118.3 A03.F1 277.5,119.83 275.84,121.47 275.84,122.87 270.51,128.21 268.99,128.21 A04.C1 | A02.T1 290.19,88.08 290.19,89.47 287.91,91.76 286.38,91.76 284.86,93.28 A02.R2 | v247.65,122.24 247.65,121.98 248.67,120.97 250.19,120.97 251.71,119.44 A05.F1 253.11,118.68 254.25,117.54 v256.41,117.54 | 235.14,97.79 233.68,99.25 A06.N2 | 235.14,97.79 235.33,97.6 235.33,96.2 236.47,95.06 237.36,95.06 238.38,94.04 239.01,94.04 A06.R1 | v235.08,101.66 229.87,106.87 230.76,107.76 231.52,107.76 232.54,106.74 232.66,106.74 A06.L2 | v232.79,95.57 233.04,95.31 233.04,94.42 A06.R2 | v244.47,102.04 245.75,100.78 A05.N2 | A06.K1 243.21,108.78 243.33,108.78 245.36,106.74 A05.L2 | v238.89,109.16 235.71,112.33 234.06,112.33 A06.J2 | v235.08,97.73 235.14,97.79 | 250.44,90.36 250.44,89.72 252.09,88.08 A05.T1 253.11,86.93 254.63,85.41 256.16,85.41 257.05,84.52 261.24,84.52 A04.U2 | 250.44,90.36 250.44,91.12 248.28,93.28 246.76,93.28 A05.R2 245.75,94.42 245.62,94.55 245.62,96.08 242.06,99.63 240.41,99.63 A06.N1 | v250.82,90.36 250.44,90.36 | v256.41,94.81 257.18,94.04 258.06,94.04 A04.R2 | A06.T1 240.03,86.55 240.03,86.04 241.55,84.52 241.55,79.69 242.19,79.06 242.95,79.06 244.86,80.96 244.86,81.6 248.16,84.9 248.54,84.52 A05.U2
  Top 0.381: A06.F1 239.01,119.44 238.63,119.83 v235.33,119.83 235.08,120.21 v235.08,124.27 | v238.25,127.57 237.62,128.21 237.24,128.21 A06.C2 | v260.35,129.73 261.11,128.97 261.24,128.97 A04.C2 | v245.62,127.06 245.36,127.32 245.11,127.32 244.22,128.21 243.59,128.21 A06.C1 | A05.K1 255.91,108.78 256.03,108.78 258.06,106.74 A04.L2 259.08,105.6 259.08,104.2 261.37,101.92 262.64,101.92 262.89,101.66 v263.27,101.41 263.4,101.41 264.41,100.39 A04.N1 | A04.K1 268.61,108.78 268.73,108.78 270.76,106.74 A03.L2 272.16,105.98 273.69,104.46 275.21,104.46 277.5,102.17 277.5,100.78 A03.N1 | 269.37,116.65 269.49,116.52 269.49,115.13 271.14,113.47 A03.J2 | 269.37,116.65 268.61,117.41 268.61,117.92 267.84,118.68 265.81,118.68 A04.F1 | 269.37,116.65 v269.62,116.9 | v269.24,101.79 270.64,100.39 270.76,100.39 A03.N2 | A03.A1 280.67,134.18 280.67,129.35 A03.C1 281.69,128.33 286.64,128.33 A02.C2 288.04,128.21 292.35,128.21 | A01.A1 306.07,134.18 306.07,129.35 A01.C1 305.69,128.21 302.01,128.21 | 292.35,128.21 292.99,128.21 A02.C1 | A02.A1 293.37,134.18 293.37,129.35 A02.C1 | A01.F2 296.55,119.83 296.55,123.89 292.35,128.08 292.35,128.21 | A02.C1 294.39,128.21 299.34,128.21 A01.C2 300.74,128.21 302.01,128.21 | v279.4,92.52 278.64,93.28 278.51,93.28 A03.R1 | A02.R1 289.81,94.04 288.29,94.04 286.13,96.2 286.13,97.6 284.48,99.25 A02.N2 | A01.R1 302.89,94.42 302.89,99.25 A01.N1 302.89,100.78 302.89,104.46 301.62,105.73 301.62,106.11 298.83,108.9 298.83,110.3 297.18,111.95 A01.J2 296.55,113.47 294.89,115.13 294.89,116.52 292.74,118.68 291.21,118.68 A02.F1 | A02.K1 294,108.78 294.13,108.78 296.16,106.74 A01.L2
  Top 0.381: A01.K1 306.07,110.3 306.07,114.36 305.18,115.25 305.18,116.65 303.53,118.3 A01.F1 302.89,119.83 302.01,120.71 302.01,128.21 | A04.A1 268.61,134.18 268.61,132.78 270.89,130.49 272.42,130.49 273.94,128.97 A03.C2 | v259.97,98.36 259.08,99.25 A04.N2 | B05.N2 246.76,29.78 247.27,29.27 248.79,29.27 250.44,27.62 250.44,26.23 252.09,24.57 B05.R1 253.11,23.43 254.63,23.43 259.97,18.1 259.97,16.7 261.62,15.05 B04.U2 | B04.N2 259.08,29.4 259.21,29.4 260.22,28.38 260.22,26.86 261.37,25.72 262.89,25.72 264.41,24.19 B04.R1 | B04.F1 265.43,48.45 265.43,47.05 267.72,44.77 269.24,44.77 270.76,43.24 B03.J2 | 294.89,50.86 v292.61,50.86 | 294.89,50.86 296.16,49.59 B01.F2 297.18,48.45 297.18,47.05 301.37,42.86 | B01.C2 299.72,59.5 299.72,60.9 297.43,63.18 295.91,63.18 294.39,64.71 B02.A1 | 294.89,50.86 294.89,57.09 294,57.98 B02.C1 | 301.37,42.86 302.89,44.39 302.89,48.45 B01.F1 | 301.37,42.86 302.64,41.59 304.17,41.59 305.69,40.07 B01.K1 306.07,38.92 306.07,35.24 302.39,31.56 303.02,30.92 B01.N1 302.89,29.4 302.89,24.57 B01.R1 302.89,23.05 302.89,18.22 B01.T1 | v309.12,61.91 306.7,64.33 B01.A1 | B02.T1 290.19,18.22 290.19,23.05 B02.R1 291.21,23.43 296.16,23.43 B01.R2 296.55,24.57 296.55,25.97 294.26,28.26 292.74,28.26 291.21,29.78 B02.N1 | 283.08,37.15 283.21,37.15 283.46,36.89 B02.L2 | 283.08,37.15 280.67,37.15 271.78,46.04 271.78,48.45 B03.F2 | B03.K1 281.31,38.92 281.43,38.92 283.08,37.27 283.08,37.15 | B02.K1 294,38.92 294.13,38.92 296.16,36.89 B01.L2 | B03.R1 277.5,23.05 277.5,18.22 B03.T1 | B02.R2 283.46,23.43 278.51,23.43 B03.R1 | B03.R1 277.11,23.43 272.16,23.43 B03.R2 271.14,24.57 271.14,29.4 B03.N2 271.14,30.92 271.14,35.75 B03.L2 270.76,36.89 268.73,38.92 268.61,38.92 B04.K1 267.59,40.07 263.4,40.07 262.51,40.96 260.99,40.96 259.46,42.48 B04.J2 258.06,43.24 256.54,44.77 255.02,44.77 252.73,47.05 252.73,48.45 B05.F1 251.71,49.59 250.32,50.99 v250.19,50.99
  Top 0.381: v193.68,54.29 189.61,58.36 186.44,58.36 B10.C2 185.04,59.12 184.91,59.12 v184.15,59.88 | v229.74,62.17 229.87,62.04 229.87,59.5 B07.C1 230.89,58.36 231.01,58.23 v233.68,58.23 | 217.42,54.29 218.69,53.02 218.69,51.63 220.34,49.97 B07.F2 221.36,48.83 222.5,47.69 v224.41,47.69 | 217.42,54.29 213.36,58.36 211.84,58.36 B08.C2 | 217.42,54.29 v217.55,54.42 | v225.17,57.34 225.04,57.34 224.28,58.1 B07.C2 | v205.87,54.8 203.84,56.83 201.29,56.83 199.77,58.36 199.14,58.36 B09.C2 | B02.F2 283.85,49.97 283.85,51.37 278.38,56.83 276.86,56.83 275.34,58.36 B03.C2 274.32,59.5 274.32,60.9 272.03,63.18 270.51,63.18 268.99,64.71 B04.A1 | B02.C2 287.02,59.5 287.02,60.9 284.73,63.18 283.21,63.18 281.69,64.71 B03.A1 | B04.F2 258.06,49.59 256.54,49.59 251.21,54.93 251.21,56.33 249.56,57.98 B05.C2 | B04.C2 261.24,59.12 259.71,59.12 257.56,61.28 257.56,62.67 255.91,64.33 B05.A1 | v265.3,60.13 266.32,59.12 267.59,59.12 B04.C1 | v225.81,19.49 226.69,18.61 226.69,18.22 B07.T1 | v222.5,28 221.11,29.4 220.98,29.4 B07.N2 220.34,30.92 219.71,31.56 v219.71,32.45 | v231.39,38.04 230.5,38.92 B07.K1 | B05.T1 252.09,18.22 252.09,18.73 251.08,19.75 251.08,20.64 249.81,21.91 248.28,21.91 246.76,23.43 B05.R2 | B05.K1 255.91,38.92 256.03,38.92 258.06,36.89 B04.L2 | 231.08,24.26 235.97,19.37 237.49,19.37 239.01,17.84 B06.T1 | 231.08,24.26 227.33,28 227.33,29.4 B07.N1 | 231.08,24.26 v231.01,24.19 | v218.95,38.67 220.34,37.27 B07.L2 | v294.39,71.18 286.89,78.68 286.89,79.31 285.37,80.83 285.37,81.6 280.04,86.93 278.51,86.93 A03.T1 | A20.R2 55.24,94.42 55.24,99.25 A20.N2 55.24,100.78 55.24,105.09
  Top 0.381: 55.24,105.09 55.24,105.6 A20.L2 55.24,107.12 55.24,111.95 A20.J2 55.24,113.47 55.24,118.3 A20.F2 | A21.F2 42.55,118.3 42.55,113.47 A21.J2 42.55,111.95 42.55,107.12 A21.L2 43.56,105.98 44.45,105.09 55.24,105.09 | A21.N2 42.55,99.25 42.55,94.42 A21.R2 43.18,92.9 44.83,91.25 44.83,89.85 45.72,88.96 45.72,84.9 A21.U2 | 29.84,98.74 29.84,99.25 A22.N2 29.84,100.78 29.84,105.6 A22.L2 29.84,107.12 29.84,111.95 A22.J2 29.84,113.47 29.84,118.3 A22.F2 | 29.84,98.74 29.84,94.42 A22.R2 30.48,92.9 32.13,91.25 32.13,89.85 33.02,88.96 33.02,84.9 A22.U2 | v23.37,60.13 31.62,60.13 32.64,59.12 B22.C2 | v38.99,56.2 37.72,56.2 37.08,56.83 35.56,56.83 34.04,58.36 B22.C2 | A23.R2 17.78,92.9 19.43,91.25 19.43,89.85 20.32,88.96 20.32,84.9 A23.U2 20.7,83.38 20.7,80.07 34.54,66.23 34.54,64.45 33.66,63.56 33.66,59.5 B22.C2 | A23.F2 17.14,118.3 17.14,113.47 A23.J2 17.14,111.95 17.14,107.12 A23.L2 17.14,105.6 17.14,100.78 A23.N2 18.16,99.63 19.05,98.74 29.84,98.74 | B16.T2 106.68,16.7 106.81,16.7 108.84,14.67 B16.U2 | B17.T2 93.98,16.7 94.11,16.7 96.14,14.67 B17.U2 | B18.T2 81.28,16.7 81.41,16.7 83.44,14.67 B18.U2 | B19.T2 68.58,16.7 68.71,16.7 70.74,14.67 B19.U2 | B20.T2 55.88,16.7 56.01,16.7 58.04,14.67 B20.U2 59.44,13.91 60.96,12.38 62.48,12.38 63.37,11.49 67.56,11.49 B19.V2 | B21.T2 43.18,16.7 43.31,16.7 45.34,14.67 B21.U2 46.74,13.91 48.26,12.38 49.78,12.38 50.67,11.49 54.86,11.49 B20.V2 | B23.T2 17.78,16.7 17.91,16.7 19.94,14.67 B23.U2 | B22.T2 30.48,16.7 30.61,16.7 32.64,14.67 B22.U2 | v103.63,62.42 104.01,62.42 105.79,60.64 107.19,60.64 108.84,58.99 B16.C2 110.24,58.61 111.51,57.34 113.67,57.34 115.44,55.56 115.82,55.56 118.24,53.15 v118.75,53.15
  Top 0.381: v65.79,54.29 61.72,58.36 59.44,58.36 B20.C2 | A19.R2 67.94,94.42 67.94,99.25 A19.N2 67.94,100.78 67.94,105.6 A19.L2 | A19.F2 67.94,118.3 67.94,113.47 A19.J2 | 77.72,66.99 62.48,82.23 60.96,82.23 59.44,83.76 A20.U2 | 77.72,66.99 83.82,60.9 83.82,59.5 B18.C2 84.84,58.36 86.36,56.83 87.88,56.83 v90.42,54.29 | 77.72,66.99 v77.6,66.86 | A13.F2 144.15,119.83 142.49,121.47 142.49,122.87 137.16,128.21 135.64,128.21 A14.C2 134.24,128.21 132.59,128.21 125.35,120.97 | v153.54,126.3 151.76,126.3 151.38,126.68 149.86,126.68 148.34,128.21 A13.C2 | v166.62,131.38 169.04,128.97 172.34,128.97 A11.C2 | v181.61,134.56 185.42,130.75 185.42,129.35 A10.C2 186.44,128.21 187.58,127.06 189.48,127.06 190.12,126.43 v192.66,126.43 | v195.58,128.46 197.74,128.46 A09.C2 199.14,128.21 200.66,126.68 202.18,126.68 202.44,126.43 v205.23,126.43 | v209.17,130.11 210.31,128.97 210.44,128.97 A08.C2 | v214.38,135.32 220.73,128.97 223.14,128.97 A07.C2 | A17.R2 93.34,94.42 93.34,99.25 A17.N2 92.96,100.39 88.77,100.39 84.71,104.46 83.19,104.46 81.66,105.98 A18.L2 | A18.R2 80.64,94.42 80.64,99.25 A18.N2 80.64,100.78 80.64,105.6 A18.L2 | A18.L2 80.64,107.12 80.64,111.95 A18.J2 80.64,113.47 80.64,118.3 A18.F2 | v140.97,55.05 138.3,57.72 137.03,57.72 136.4,58.36 135.64,58.36 B14.C2 | 163.19,58.99 162.31,58.1 161.54,58.1 161.29,58.36 161.04,58.36 B12.C2 | 163.19,58.99 162.31,59.88 161.8,59.88 v156.08,65.6 | v171.2,60.52 172.47,59.24 B11.C2 173.74,58.36 174.62,57.47 v181.23,57.47 | v166.62,55.94 166.24,55.94 163.19,58.99 | v148.34,86.17 148.34,87.31 148.08,87.57 148.08,88.2 146.43,89.85 146.43,91.25 144.78,92.9 A13.R2 144.15,94.42 144.15,95.06 143,96.2 143,96.97 135.51,104.46 133.99,104.46 132.46,105.98 A14.L2 131.44,105.6 131.44,105.09
  Top 0.381: A14.R2 131.44,94.42 131.44,99.25 A14.N2 131.44,100.78 131.44,105.09 | A16.N2 106.05,99.25 106.05,94.42 A16.R2 107.06,93.28 108.58,91.76 110.11,91.76 117.35,84.52 121.54,84.52 A15.U2 122.56,83.38 124.21,81.72 124.21,80.33 144.4,60.13 145.29,60.13 146.3,59.12 146.94,59.12 B13.C2 | A17.J2 93.34,113.47 93.34,118.3 A17.F2 93.34,119.83 92.96,120.21 93.73,120.97 | 96.52,123.76 96.52,127.83 A17.C2 | 96.52,123.76 93.73,120.97 | 106.05,117.67 106.05,113.47 A16.J2 106.05,111.95 106.05,107.12 A16.L2 107.06,105.98 111.25,105.98 112.14,105.09 118.75,105.09 | 106.05,117.67 106.05,118.3 A16.F2 | 96.52,123.76 96.65,123.64 99.95,123.64 105.92,117.67 106.05,117.67 | v143.38,104.2 144.15,103.44 144.15,100.78 A13.N2 | A15.R2 118.75,94.42 118.75,99.25 A15.N2 118.75,100.78 118.75,105.09 | 118.75,105.09 118.75,105.6 A15.L2 | A15.L2 118.75,107.12 118.75,111.95 A15.J2 118.75,113.47 118.75,118.3 A15.F2 118.75,119.83 118.36,120.21 121.92,123.76 121.92,124.27 | 121.92,124.27 121.92,127.83 A15.C2 | 125.35,120.97 122.05,124.27 121.92,124.27 | 125.35,120.97 126.87,119.44 131.06,119.44 A14.F2 131.44,118.3 131.44,113.47 A14.J2 132.46,112.33 133.99,110.81 141.86,110.81 144.15,108.52 144.15,107.12 A13.L2 | 131.44,105.09 120.65,105.09 119.76,105.98 A15.L2 | A18.C2 84.84,128.21 86.49,128.21 93.73,120.97
  Bottom 0.381: A01.U2 300.74,84.52 300.74,84.64 302.77,86.68 A01.T1 | A02.U2 288.04,84.52 288.04,84.64 290.07,86.68 A02.T1 | A03.U2 275.34,84.52 275.34,84.64 277.37,86.68 A03.T1 278.51,87.69 280.04,87.69 282.19,89.85 282.19,91.5 283.72,93.03 A02.R2 284.86,94.04 286.38,94.04 288.54,96.2 288.54,97.6 290.19,99.25 A02.N1 | v247.65,122.24 246.38,120.97 246.38,119.83 A05.F2 | v256.41,117.54 257.56,118.68 258.06,118.68 A04.F2 | A02.J2 283.85,111.95 283.72,111.95 281.69,109.92 A03.K1 | A05.F1 253.11,119.44 253.87,119.44 254,119.57 255.52,119.57 261.11,125.16 263.02,125.16 264.54,126.68 266.06,126.68 267.59,128.21 A04.C1 | v235.08,101.66 233.93,100.52 A06.N2 | v232.79,95.57 233.43,95.57 235.33,97.47 | 235.33,97.47 235.97,98.11 237.49,98.11 239.01,99.63 A06.N1 240.41,100.39 242.7,100.39 244.09,101.79 v244.47,102.04 244.47,104.33 245.75,105.6 A05.L2 | v238.89,109.16 240.41,109.16 241.3,108.27 242.19,109.16 A06.K1 243.59,109.92 245.62,111.95 245.75,111.95 A05.J2 | 235.33,97.47 v235.08,97.73 | A04.U2 262.64,84.52 262.64,84.64 264.67,86.68 A04.T1 | A06.U2 237.24,84.52 237.24,84.64 239.27,86.68 A06.T1 | A05.U2 249.94,84.52 249.94,84.64 251.97,86.68 A05.T1 | A05.R1 251.97,93.03 250.95,92.01 250.95,90.49 v250.82,90.36 251.21,90.61 251.33,90.74 252.22,90.74 256.29,94.81 v256.41,94.81 256.79,95.06 256.79,95.19 v259.97,98.36 | v235.33,119.83 234.95,119.44 234.06,119.44 A06.F2 | A06.A1 242.82,134.18 242.82,129.35 A06.C1 242.19,128.21 241.55,127.57 v238.25,127.57 238,127.19 v235.08,124.27 | 260.6,129.48 261.37,130.24 261.75,130.24 264.54,133.03 266.06,133.03 266.45,133.41
  Bottom 0.381: 260.6,129.48 260.1,128.97 256.29,128.97 A05.C1 | 266.45,133.41 267.59,134.56 A04.A1 | 260.6,129.48 v260.35,129.73 | 266.45,133.41 263.65,136.21 261.37,136.21 260.48,135.32 256.29,135.32 A05.A1 255.27,134.18 253.62,132.52 253.62,131.13 251.46,128.97 249.94,128.97 A05.C2 248.54,128.21 247.4,127.06 v245.62,127.06 | A03.R2 272.16,94.04 273.69,94.04 275.84,96.2 275.84,97.6 277.5,99.25 A03.N1 | A04.R1 265.81,94.04 266.45,94.04 267.84,95.44 268.73,95.44 269.49,96.2 269.49,97.6 271.14,99.25 A03.N2 | A04.J2 258.44,111.95 258.32,111.95 256.29,109.92 A05.K1 | A05.N1 253.11,99.63 256.29,99.63 257.18,98.74 258.06,99.63 A04.N2 259.46,100.39 262.25,100.39 v263.27,101.41 | 268.99,102.04 269.49,102.55 269.49,103.95 271.14,105.6 A03.L2 | 268.99,102.04 267.08,100.14 265.81,100.14 A04.N1 | A03.J2 271.14,111.95 271.02,111.95 268.99,109.92 A04.K1 | v269.62,116.9 271.02,118.3 271.14,118.3 A03.F2 | 268.99,102.04 v269.24,101.79 | 275.97,128.21 280.29,128.21 A03.C1 | 275.97,128.21 275.34,128.21 A03.C2 | v279.4,92.52 279.4,93.41 282.19,96.2 282.19,97.6 283.85,99.25 A02.N2 284.86,100.39 286.38,100.39 291.72,105.73 291.72,107.12 293.37,108.78 A02.K1 294.39,109.92 296.42,111.95 296.55,111.95 A01.J2 297.18,113.47 298.83,115.13 298.83,116.52 300.99,118.68 302.51,118.68 A01.F1 | A02.F2 284.86,118.68 289.81,118.68 A02.F1 | A04.F1 265.81,119.44 267.33,119.44 275.97,128.08 275.97,128.21 | A01.N2 297.56,100.39 299.08,100.39 301.24,102.55 301.24,103.82 297.94,107.12 297.56,106.74 A01.L2 | B04.U2 262.64,14.67 262.64,14.8 264.67,16.83 B04.T1 265.81,17.84 267.33,17.84 269.49,20 269.49,21.4 271.14,23.05 B03.R2
  Bottom 0.381: 260.48,23.43 264.41,23.43 B04.R1 | 260.48,23.43 259.46,23.43 B04.R2 | 260.48,23.43 260.48,23.56 264.8,27.88 264.8,29.4 B04.N1 265.56,30.8 266.57,31.81 266.57,33.47 267.72,34.61 269.24,34.61 270.76,36.13 B03.L2 | B03.F1 277.5,48.45 277.5,47.94 276.35,46.8 276.35,45.91 275.21,44.77 273.69,44.77 272.16,43.24 B03.J2 271.02,42.23 268.99,40.2 268.99,40.07 B04.K1 | v292.61,50.86 291.34,49.59 291.21,49.59 B02.F1 | B02.C1 292.99,59.12 291.34,60.77 291.72,61.15 291.72,62.67 293.37,64.33 B02.A1 293.88,65.85 293.88,70.29 294.39,70.8 v294.39,71.18 | B01.F1 303.53,49.97 305.18,51.63 305.18,53.02 305.82,53.66 305.94,53.66 308.74,56.45 306.96,58.23 B01.C1 306.7,59.5 v309.12,61.91 | B01.U2 300.74,14.67 300.74,14.8 302.77,16.83 B01.T1 | B02.U2 288.04,14.67 288.04,14.8 290.07,16.83 B02.T1 | B01.N2 296.55,29.4 296.55,28 294.26,25.72 292.48,25.72 291.08,24.32 B02.R1 | B01.R1 302.51,23.43 297.56,23.43 B01.R2 | B02.J2 283.85,42.1 283.72,42.1 281.69,40.07 B03.K1 | B01.J2 296.55,42.1 296.42,42.1 294.39,40.07 B02.K1 | B03.U2 275.34,14.67 275.34,14.8 277.37,16.83 B03.T1 | B03.R1 277.5,24.57 277.5,29.4 B03.N1 278.51,29.78 279.53,29.78 | 279.53,29.78 283.46,29.78 B02.N2 | B02.R2 284.48,24.57 286.13,26.23 286.13,27.62 288.29,29.78 289.81,29.78 B02.N1 290.83,30.92 292.48,32.58 292.48,33.97 294.64,36.13 296.16,36.13 B01.L2 | B02.L2 283.85,35.75 283.85,34.23 279.53,29.91 279.53,29.78 | v193.68,54.29 195.83,54.29 196.47,54.93 196.47,56.33 198.12,57.98 B09.C2 | B07.A1 229.87,64.33 229.74,64.2 v229.74,62.17 229.49,61.78 229.49,61.66 v225.17,57.34 | v233.68,58.23 233.81,58.36 235.84,58.36 B06.C2
  Bottom 0.381: 225.17,46.93 226.69,48.45 B07.F1 | 225.17,46.93 225.04,46.8 225.04,45.4 222.88,43.24 221.36,43.24 B07.J2 220.34,42.1 220.34,40.07 v218.95,38.67 | v217.55,54.42 221.49,58.36 223.14,58.36 B07.C2 | v224.41,47.69 225.17,46.93 | v205.87,54.8 205.87,55.31 207.39,56.83 208.91,56.83 210.44,58.36 B08.C2 | B03.C2 275.34,58.36 280.29,58.36 B03.C1 280.67,59.5 280.67,64.33 B03.A1 | 249.94,51.24 253.62,54.93 253.62,59.37 253.11,59.88 254,60.77 | 249.94,51.24 248.28,49.59 246.76,49.59 B05.F2 | 254,60.77 254.76,60.77 255.65,59.88 255.27,59.5 B05.C1 | 253.75,63.56 254.89,64.71 B05.A1 | 253.75,63.56 253.37,63.18 251.84,63.18 249.56,60.9 249.56,59.5 B05.C2 | B04.C2 262.64,59.12 263.65,60.13 v265.3,60.13 265.56,60.52 267.97,62.93 267.97,64.33 B04.A1 | 254,60.77 253.87,60.9 253.87,63.44 253.75,63.56 | B07.U2 224.54,14.67 224.54,14.8 226.57,16.83 B07.T1 | 231.27,23.94 240.66,33.34 241.05,33.34 242.32,34.61 243.84,34.61 245.36,36.13 B05.L2 | 231.27,23.94 230.76,23.43 227.71,23.43 B07.R1 226.69,23.05 225.81,22.16 v225.81,19.49 | 222.76,27.75 223.27,28.26 224.79,28.26 226.31,29.78 B07.N1 227.33,30.92 228.98,32.58 228.98,33.97 231.39,36.39 v231.39,38.04 | 222.76,27.75 220.98,25.97 220.98,24.57 B07.R2 | v222.5,28 222.76,27.75 | v219.71,32.45 220.34,33.08 220.34,35.75 B07.L2 | B05.U2 249.94,14.67 249.94,14.8 251.97,16.83 B05.T1 | B06.T1 240.41,17.84 241.94,17.84 244.09,20 244.09,21.4 245.75,23.05 B05.R2 246.76,24.19 248.28,24.19 250.44,26.35 250.44,27.75 252.09,29.4 B05.N1 253.11,30.54 254.63,30.54 256.79,32.7 256.79,34.1 258.44,35.75 B04.L2 | B05.J2 246.76,43.24 248.28,43.24 250.44,45.4 250.44,46.8 252.09,48.45 B05.F1
  Bottom 0.381: B04.J2 258.44,42.1 258.32,42.1 256.29,40.07 B05.K1 | v231.01,24.19 231.27,23.94 | v250.19,50.99 249.94,51.24 | 58.42,123.76 58.42,127.83 A20.C2 | 58.42,123.76 57.53,122.87 57.53,121.47 55.88,119.83 A20.F2 | 45.72,126.68 45.72,123.76 44.83,122.87 44.83,121.47 43.18,119.83 A21.F2 | 45.72,126.68 45.72,127.83 A21.C2 | 33.02,126.68 33.02,123.76 32.13,122.87 32.13,121.47 30.48,119.83 A22.F2 | 33.02,126.68 33.02,127.83 A22.C2 | A21.R2 42.16,93.28 40.64,93.28 35.31,87.95 35.31,86.55 33.66,84.9 A22.U2 | 45.72,126.68 33.02,126.68 | v23.37,60.13 22.35,59.12 21.34,59.12 B23.C2 | v38.99,56.2 41.15,58.36 45.34,58.36 B21.C2 | A23.R2 17.14,94.42 17.14,99.25 A23.N2 | A23.C2 20.32,127.83 20.32,123.76 19.43,122.87 19.43,121.47 17.78,119.83 A23.F2 | B16.V2 107.06,11.49 107.06,11.62 109.09,13.65 B16.U2 | B17.V2 94.23,11.62 94.23,11.75 96.27,13.78 B17.U2 97.54,14.67 97.79,14.92 101.98,14.92 104.14,17.08 105.66,17.08 B16.T2 | B18.V2 81.66,11.49 81.66,11.62 83.69,13.65 B18.U2 84.84,14.67 86.36,16.19 87.88,16.19 88.77,17.08 92.96,17.08 B17.T2 | B19.V2 68.96,11.49 68.96,11.62 70.99,13.65 B19.U2 72.14,14.67 73.66,16.19 75.18,16.19 76.07,17.08 80.26,17.08 B18.T2 | B20.V2 56.26,11.49 56.26,11.62 58.29,13.65 B20.U2 | B21.V2 43.56,11.49 43.56,11.62 45.59,13.65 B21.U2 | B23.U2 21.34,14.67 25.53,14.67 26.42,15.56 27.94,15.56 29.46,17.08 B22.T2 | 38.48,17.08 37.97,17.08 37.08,16.19 35.56,16.19 34.04,14.67 B22.U2 | 38.48,17.08 42.16,17.08 B21.T2 | v103.63,62.42 100.33,59.12 97.54,59.12 B17.C2 96.52,57.98 96.52,56.58 94.23,54.29 v90.42,54.29 | v118.75,53.15 118.87,53.15 121.92,56.2 121.92,57.98 B15.C2
  Bottom 0.381: A20.U2 59.44,84.52 60.96,84.52 67.56,91.12 67.56,92.52 67.94,92.9 A19.R2 | A19.J2 67.94,111.95 67.94,107.12 A19.L2 | 71.12,123.76 71.12,127.83 A19.C2 | 70.87,123.51 70.23,122.87 70.23,121.47 68.58,119.83 A19.F2 | 71.12,123.76 70.87,123.51 | v77.6,66.86 71.75,61.02 71.75,59.5 B19.C2 70.74,58.36 69.22,56.83 67.69,56.83 66.67,55.82 66.67,55.18 v65.79,54.29 65.41,54.55 59.94,49.09 59.94,45.4 45.97,31.43 42.29,31.43 38.48,27.62 38.48,17.08 | 58.42,123.76 58.55,123.64 70.74,123.64 70.87,123.51 | A13.C2 147.32,127.83 147.32,124.52 145.8,123 145.8,120.84 144.78,119.83 A13.F2 | v153.54,126.3 155.45,128.21 159.64,128.21 A12.C2 161.04,128.97 162.56,130.49 164.08,130.49 164.97,131.38 v166.62,131.38 | v181.61,134.56 180.85,134.56 176.78,130.49 175.26,130.49 173.74,128.97 A11.C2 | v195.58,128.46 194.69,128.46 v192.66,126.43 | v205.23,126.43 208.91,130.11 v209.17,130.11 209.42,130.49 214.25,135.32 v214.38,135.32 | A18.U2 84.84,84.52 86.36,84.52 91.69,89.85 91.69,91.25 93.34,92.9 A17.R2 | A19.U2 72.14,84.52 73.66,84.52 78.99,89.85 78.99,91.25 80.64,92.9 A18.R2 | 83.57,123.51 82.93,122.87 82.93,121.47 81.28,119.83 A18.F2 | 83.57,123.51 83.82,123.76 83.82,127.83 A18.C2 | v140.97,55.05 142.11,55.05 143.89,56.83 145.41,56.83 146.94,58.36 B13.C2 148.34,59.12 149.86,60.64 151.38,60.64 156.08,65.34 v156.08,65.6 | v166.62,55.94 v171.2,60.52 | A14.U2 135.25,84.9 135.25,86.3 140.72,91.76 142.24,91.76 143.76,93.28 A13.R2 | v148.34,86.17 147.96,85.79 147.96,84.9 A13.U2 | A13.J2 144.15,111.95 144.15,110.55 135.51,101.92 133.99,101.92 132.46,100.39 A14.N2 | A17.U2 97.54,84.52 99.06,84.52 104.39,89.85 104.39,91.25 106.05,92.9 A16.R2 107.06,94.04 111.25,94.04 115.32,98.11 116.84,98.11 118.36,99.63 A15.N2
  Bottom 0.381: A17.L2 93.34,107.12 93.34,111.95 A17.J2 | A16.C2 109.22,127.83 109.22,123.76 108.33,122.87 108.33,121.47 106.68,119.83 A16.F2 | v143.38,104.2 143.38,104.84 144.15,105.6 A13.L2 | A16.U2 110.24,84.52 111.76,84.52 117.09,89.85 117.09,91.25 118.75,92.9 A15.R2 | 71.12,123.76 71.25,123.64 83.44,123.64 83.57,123.51 | v184.15,59.88 183.64,59.88 v181.23,57.47
I_3CYCLE  (via drill 0.61)
  Top 0.152: v111.89,9.21 72.26,48.83 68.96,48.83 B19.F2 | v177.67,52.77 177.67,52.51 178.94,51.24 184.02,51.24 v185.29,49.97 | v213.74,68.52 214,68.52 214.63,67.88 219.46,67.88 219.84,67.5 | 219.84,67.5 245.62,41.72 246.89,41.72 248.54,40.07 B05.K2 | v262.76,98.74 256.29,105.22 251.97,105.22 249.56,107.63 249.56,108.78 A05.K2 | v235.97,74.49 235.33,74.49 234.95,74.87 233.81,74.87 v229.87,78.8 | 219.84,67.5 v219.96,67.63
  Bottom 0.152: v111.89,9.21 134.11,9.21 v177.67,52.77 | v185.29,49.97 186.69,49.97 200.91,64.2 202.31,64.2 204.34,66.23 209.04,66.23 209.93,67.12 212.34,67.12 v213.74,68.52 | v262.76,98.74 262.25,98.74 248.03,84.52 246,84.52 v235.97,74.49 | v229.87,78.8 229.87,78.68 226.95,75.75 226.95,74.61 v219.96,67.63
I_AC00  (via drill 0.61)
  Top 0.152: v127.51,78.3 130.56,78.3 v134.87,73.98 | v186.18,120.33 186.18,120.21 188.47,117.92 v190.5,117.92 | v215.01,141.29 215.39,141.29 v228.09,128.59 | v230.12,130.62 230.38,130.62 236.22,124.78 236.22,124.65 244.35,116.52 244.35,116.01 250.32,110.05 250.32,109.67 v250.82,109.16 | v275.97,60.52 275.34,60.52 272.16,63.69 271.27,63.69 268.73,66.23 266.83,66.23 v265.18,67.88 | v283.59,89.34 283.59,90.23 282.7,91.12 282.7,91.63 273.56,100.78 273.05,100.78 v264.41,109.41 | v263.14,110.68 262.38,110.68 v258.19,114.87
  Bottom 0.152: v127.51,78.3 106.68,57.47 106.68,56.33 B16.D2 | v134.87,73.98 139.06,73.98 149.99,84.9 150.88,84.9 186.18,120.21 v186.18,120.33 | v190.5,117.92 191.64,117.92 v215.01,141.29 | v228.09,128.59 v230.12,130.62 | v250.82,109.16 251.71,109.16 252.6,110.05 254,110.05 258.19,114.24 | 258.19,114.24 258.7,114.75 258.95,114.75 265.68,121.47 265.94,121.47 274.19,129.73 275.46,129.73 277.11,131.38 A03.B1 | v275.97,60.52 276.99,61.53 277.11,61.53 B03.B1 | v265.18,67.88 265.68,67.88 268.73,70.93 268.73,71.18 268.99,71.44 268.99,71.82 269.11,71.94 269.11,72.58 269.24,72.71 269.24,74.99 v283.59,89.34 | v263.14,110.68 v264.41,109.41 | 258.19,114.24 v258.19,114.87
I_AC01  (via drill 0.61)
  Top 0.152: v193.68,129.67 193.68,129.16 209.42,113.41 209.42,112.52 210.82,111.12 211.2,111.12 215.39,106.93 215.39,105.79 213.36,103.76 | 213.36,103.76 v209.93,107.19 | v261.49,139.19 270.64,130.05 271.53,130.05 274.07,127.51 275.46,127.51 277.11,125.86 A03.D1 | v280.54,55.88 280.54,56.01 v277.24,59.31 | v276.73,66.67 v279.4,64.01 | v285.75,76.71 285.75,77.72 v275.08,88.39 | v269.88,86.23 269.75,86.23 v268.22,87.76 | v254.38,75.69 253.87,75.69 v247.52,82.04 | v243.97,85.34 v243.97,81.41 | v235.33,77.6 235.08,77.6 222.76,89.92 222.76,94.36 213.36,103.76
  Bottom 0.152: v193.68,129.67 191.52,129.67 153.16,91.31 150.24,91.31 121.92,62.99 118.49,62.99 106.81,51.31 106.81,49.91 B16.F2 | v209.93,107.19 210.44,107.19 212.22,108.97 212.22,112.27 223.27,123.32 223.52,123.32 225.17,124.97 225.17,126.87 236.85,138.56 237.87,138.56 238,138.68 248.67,138.68 249.17,139.19 v261.49,139.19 | v280.54,55.88 278.51,55.88 B03.D1 | v277.24,59.31 277.24,59.69 278.89,61.34 278.89,63.5 v279.4,64.01 | v276.73,66.67 276.73,67.69 v285.75,76.71 | v275.08,88.39 274.19,88.39 272.03,86.23 v269.88,86.23 | v268.22,87.76 267.72,87.76 262.64,82.68 261.87,82.68 261.24,82.04 258.19,82.04 257.68,81.53 257.68,78.99 v254.38,75.69 | v247.52,82.04 244.6,82.04 v243.97,81.41 | v243.97,85.34 242.57,85.34 242.44,85.22 242.32,85.22 242.32,85.09 242.19,85.09 242.19,84.96 242.06,84.96 242.06,84.84 241.94,84.84 241.94,84.71 241.81,84.71 241.81,84.58 239.27,82.04 239.14,82.04 239.14,81.92 239.01,81.92 239.01,81.79 238.89,81.79 238.89,81.66 238.76,81.66 238.76,81.53 238.63,81.53 238.63,80.9 v235.33,77.6
I_AC02  (via drill 0.61)
  Top 0.152: v126.11,32.07 116.46,41.72 112.27,41.72 111.51,42.48 107.06,42.48 B16.J2 | v155.07,50.35 158.62,50.35 161.16,47.82 162.18,47.82 v188.98,21.02 | v201.8,33.21 201.8,32.58 207.39,26.99 208.03,26.99 223.77,11.24 224.28,11.24 224.66,10.86 225.68,10.86 226.57,9.97 228.6,9.97 v230.38,8.19 | v307.47,85.41 301.88,91 301.88,92.77 301.24,93.41 301.24,100.9 301.12,101.03 301.12,103.69 289.43,115.38 289.43,115.89 283.46,121.86 281.69,121.86 A03.E1 | v288.29,47.43 284.35,47.43 283.08,48.7 283.08,49.85 281.31,51.63 B03.E1
  Bottom 0.152: v126.11,32.07 131.57,32.07 147.07,47.56 152.27,47.56 v155.07,50.35 | v188.98,21.02 189.61,21.02 v201.8,33.21 | v230.38,8.19 232.92,8.19 244.6,19.88 244.6,20.64 246.51,22.54 248.54,22.54 252.98,26.99 254,26.99 277.37,50.35 278.64,50.35 280.29,52.01 B03.E1 | v307.47,85.41 307.47,72.83 305.82,71.18 305.82,70.67 303.53,68.39 303.53,66.99 301.12,64.58 301.12,62.8 296.8,58.48 296.8,57.09 295.78,56.07 295.78,52.9 290.96,48.07 288.93,48.07 v288.29,47.43
I_AC03  (via drill 0.61)
  Top 0.152: v118.49,45.53 120.02,45.53 140.97,24.57 142.11,24.57 153.54,13.14 156.21,13.14 156.46,12.89 159.13,12.89 v164.08,7.94 | v190.12,28.64 192.28,28.64 v219.2,1.71 | v244.47,18.61 247.27,18.61 253.37,12.51 255.27,12.51 258.19,9.59 259.33,9.59 259.59,9.34 260.73,9.34 v261.49,8.57 | v275.72,28.26 274.83,28.26 273.56,29.53 273.56,34.86 v273.05,35.37 | B03.H1 281.31,45.28 281.43,45.15 v281.43,43.75 281.81,43.5 v287.27,38.04 | v276.86,108.9 282.57,103.19 282.57,103.06 284.48,101.16 284.61,101.16 291.59,94.17 291.59,90.61 307.72,74.49 307.72,68.14 v309.12,66.74
  Bottom 0.152: v118.49,45.53 109.86,36.89 107.06,36.89 B16.L2 | v164.08,7.94 167.13,7.94 169.04,9.84 171.32,9.84 v190.12,28.64 | v219.2,1.71 219.96,0.95 224.79,0.95 226.06,2.22 226.69,2.22 227.33,2.86 228.22,2.86 230.38,5.02 230.89,5.02 v244.47,18.61 | v261.49,8.57 264.16,8.57 275.72,20.13 v275.72,28.26 | v273.05,35.37 v281.43,43.75 | v276.86,108.9 280.67,112.71 280.67,115.13 A03.H1 | v309.12,66.74 309.12,63.06 302.13,56.07 302.13,52.9 v287.27,38.04
I_AC04  (via drill 0.61)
